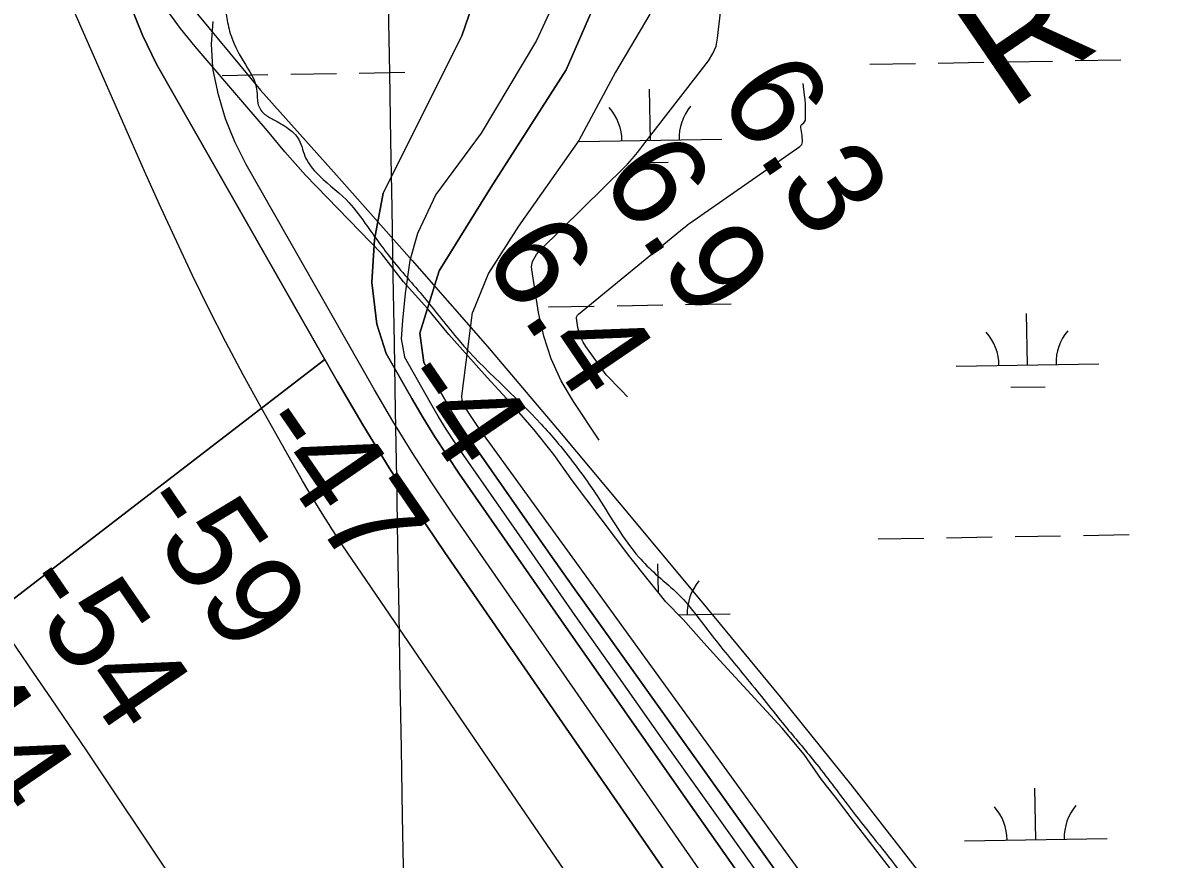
# Model space of a CAD drawing. Extents: x 3892998 to 3931244, y 278583 to 304547.
# Drawn here: x 3912822 to 3913620, y 291075 to 291661 of the extents above; entities that cross this region are included whole.
import ezdxf

# ---------------------------------------------------------------- set-up
doc = ezdxf.new("R2010")
doc.units = 0
for name, color, linetype in [('V-GRID-MAJR', 7, 'Continuous'), ('V-RIVR-EDGE', 7, 'Continuous'), ('V-RIVR-RANG', 7, 'Continuous'), ('V-RIVR-RANG-IDEN', 7, 'Continuous'), ('V-RRAP-FSHR', 7, 'Continuous'), ('V-TOPO-DPTH', 7, 'Continuous'), ('V-TOPO-MAJR', 7, 'Continuous'), ('V-TOPO-MINR', 7, 'Continuous'), ('V-TOPO-WATR', 7, 'Continuous'), ('V-WETL-SWMP', 7, 'Continuous')]:
    doc.layers.add(name, color=color, linetype=linetype)

msp = doc.modelspace()

# ---------------------------------------------------------------- linework, layer by layer
at = {"layer": 'V-GRID-MAJR'}
msp.add_spline([(3913205.694, 284291.167), (3913100.856, 290347.625), (3912995.9590000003, 296407.553), (3912891.061, 302467.47500000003), (3912891.001, 302470.95)], degree=3, dxfattribs=at)
at = {"layer": 'V-RIVR-EDGE'}
msp.add_spline([(3912905.462429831, 291820.09187449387), (3912916.1993131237, 291798.1348694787), (3912921.3932742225, 291786.9827471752), (3912931.4339568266, 291765.0274636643), (3912935.9162236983, 291747.61125666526), (3912940.4122626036, 291735.7646551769), (3912954.9722244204, 291711.36147947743), (3912961.5198530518, 291684.5413986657), (3912964.258175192, 291665.73709404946), (3912967.0128516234, 291653.54669597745), (3912976.0161192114, 291634.37879747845), (3912985.7104229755, 291613.1205754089), (3912986.385104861, 291604.416345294), (3912990.545093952, 291597.4440093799), (3912997.1486714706, 291593.25045095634), (3913007.576188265, 291586.9588221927), (3913014.1746012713, 291580.67666170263), (3913019.3633978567, 291567.43593733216), (3913026.994061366, 291556.2777897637), (3913048.1808410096, 291537.07976494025), (3913061.368198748, 291520.68634017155), (3913079.061924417, 291496.62351804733), (3913103.011127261, 291468.3679982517), (3913127.304126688, 291438.37111598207), (3913184.9441775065, 291379.7473732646), (3913206.1163243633, 291354.63164258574), (3913225.1955653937, 291327.780574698), (3913253.290124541, 291286.6350131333), (3913265.0962706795, 291274.77033585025), (3913279.3373977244, 291262.20343261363), (3913304.672976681, 291231.5077673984), (3913329.3132157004, 291201.16192403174), (3913355.687931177, 291168.3750744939), (3913376.51197769, 291143.26020456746), (3913400.8006733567, 291111.5228205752), (3913434.460534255, 291068.62298525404), (3913468.459887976, 291022.24128573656), (3913495.173235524, 290985.624471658), (3913514.60143765, 290959.12064336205), (3913570.4347088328, 290873.69747788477), (3913590.894300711, 290841.9695621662), (3913606.505449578, 290820.3486069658), (3913627.3217493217, 290792.10083393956), (3913641.190674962, 290769.7879818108), (3913669.62730919, 290726.20485708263), (3913686.621391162, 290700.7513550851), (3913705.714404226, 290679.46989270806), (3913722.034665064, 290663.06872116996), (3913741.1182098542, 290637.958155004), (3913763.668125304, 290606.9212754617), (3913781.0301049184, 290589.47322063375)], degree=3, dxfattribs=at)
at = {"layer": 'V-RRAP-FSHR'}
msp.add_lwpolyline([(3912906.2273111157, 291748.72141911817), (3912937.3302871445, 291675.2780910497), (3912988.1370711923, 291613.8770029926), (3913041.368687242, 291554.15732293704), (3913094.463087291, 291494.31885888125), (3913147.23595134, 291434.1936748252), (3913198.9479513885, 291373.15508276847), (3913250.2749274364, 291311.79495471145), (3913301.436015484, 291250.29351465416), (3913352.4148315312, 291188.64052259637), (3913402.6399835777, 291126.37722653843), (3913451.671151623, 291063.17799447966), (3913498.9103196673, 290998.61479441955), (3913544.746607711, 290933.480202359), (3913590.484591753, 290867.4137702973), (3913636.3208797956, 290801.84705023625)], dxfattribs=at)
at = {"layer": 'V-TOPO-DPTH'}
for points in [[(3913076.2252892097, 291429.3480772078), (3913069.6821606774, 291449.8861347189), (3913066.3242387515, 291479.06537268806), (3913068.1135175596, 291509.0898517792), (3913074.196726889, 291541.67761922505), (3913129.3501844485, 291651.7902147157), (3913156.5586192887, 291731.2995302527), (3913180.836297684, 291839.3435509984), (3913194.683691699, 291977.44226630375), (3913191.957129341, 292088.5559511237), (3913158.727274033, 292358.27516429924)], [(3913158.727274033, 292358.27516429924), (3913191.957129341, 292088.5559511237), (3913194.683691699, 291977.44226630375), (3913180.836297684, 291839.3435509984), (3913156.5586192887, 291731.2995302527), (3913129.3501844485, 291651.7902147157), (3913074.196726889, 291541.67761922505), (3913068.1135175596, 291509.0898517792), (3913066.3242387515, 291479.06537268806), (3913069.6821606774, 291449.8861347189), (3913076.2252892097, 291429.3480772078)], [(3912897.1451768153, 291673.0771983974), (3912905.4272677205, 291652.21579509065), (3912915.4203108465, 291631.9170253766), (3913041.9467947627, 291409.9072882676), (3913059.8933273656, 291379.3466368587), (3913078.3588966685, 291349.1123106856), (3913097.603021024, 291319.3674723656), (3913117.366182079, 291289.94895928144), (3913483.676371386, 290759.6812828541), (3913486.861552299, 290755.08465931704), (3913490.055569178, 290750.49420277), (3913493.2628400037, 290745.9129967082), (3913496.478946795, 290741.33795763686), (3913501.5266543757, 290734.17940441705), (3913502.217506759, 290733.1829194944), (3913502.897661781, 290732.1793083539), (3913504.2151823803, 290730.1435812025), (3913507.847480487, 290724.36477111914), (3913510.3003555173, 290720.4432378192), (3913512.741687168, 290716.51456646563), (3913515.165703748, 290712.5751880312), (3913517.578176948, 290708.6286715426), (3913604.584874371, 290565.5897350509), (3913651.4089650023, 290490.7297236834)], [(3912897.1451768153, 291673.0771983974), (3912905.4272677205, 291652.21579509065), (3912915.4203108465, 291631.9170253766), (3913033.3308464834, 291425.02526478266)], [(3913222.0146481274, 291673.01029888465), (3913202.394844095, 291628.0154578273), (3913149.6679661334, 291545.56635172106), (3913113.5076193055, 291487.0994041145), (3913099.8941203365, 291443.5911563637), (3913102.566354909, 291422.9241536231)], [(3913321.2006484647, 291030.7864036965), (3913122.5521167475, 291317.35974646), (3913108.2683274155, 291338.5591510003), (3913094.365688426, 291359.9986182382), (3913081.0347749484, 291381.7981795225), (3913068.085011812, 291403.8378035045), (3912978.057272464, 291561.80541846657), (3912970.2037428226, 291577.5384197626), (3912963.554142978, 291593.69153764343), (3912958.7104378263, 291610.4748304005), (3912955.0706624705, 291627.6782397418), (3912954.7258265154, 291629.9073004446), (3912953.863987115, 291646.025871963), (3912955.0475181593, 291661.7856191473)], [(3913321.2006484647, 291030.7864036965), (3913122.5521167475, 291317.35974646), (3913108.2683274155, 291338.5591510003), (3913094.365688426, 291359.9986182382), (3913081.0347749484, 291381.7981795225), (3913068.085011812, 291403.8378035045), (3912978.057272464, 291561.80541846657), (3912970.2037428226, 291577.5384197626), (3912963.554142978, 291593.69153764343), (3912958.7104378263, 291610.4748304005), (3912955.0706624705, 291627.6782397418), (3912954.7258265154, 291629.9073004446), (3912953.863987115, 291646.025871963), (3912955.0475181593, 291661.7856191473)], [(3913736.7739366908, 290460.95166721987), (3913565.6152656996, 290720.6767830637), (3913552.1224241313, 290740.91804081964), (3913538.4882412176, 290761.0625437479), (3913524.6420462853, 290781.0619144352), (3913510.6545100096, 290800.96453029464), (3913377.8013416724, 290987.8925058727), (3913332.7934826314, 291051.4249503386), (3913287.915268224, 291115.048546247), (3913243.2315207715, 291178.80886931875), (3913198.6774179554, 291242.6603438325), (3913127.6844999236, 291344.73357149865), (3913118.9028194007, 291357.7295626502), (3913110.359043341, 291370.87565585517), (3913102.1721239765, 291384.2469021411), (3913094.223109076, 291397.7682504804), (3913076.2252892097, 291429.3480772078)], [(3913076.2252892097, 291429.3480772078), (3913094.223109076, 291397.7682504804), (3913102.1721239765, 291384.2469021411), (3913110.359043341, 291370.87565585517), (3913118.9028194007, 291357.7295626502), (3913127.6844999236, 291344.73357149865), (3913198.6774179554, 291242.6603438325), (3913243.2315207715, 291178.80886931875), (3913287.915268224, 291115.048546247), (3913332.7934826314, 291051.4249503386), (3913377.8013416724, 290987.8925058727), (3913510.6545100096, 290800.96453029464), (3913524.6420462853, 290781.0619144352), (3913538.4882412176, 290761.0625437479), (3913552.1224241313, 290740.91804081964), (3913565.6152656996, 290720.6767830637), (3913736.7739366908, 290460.95166721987)], [(3913033.3308464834, 291425.02526478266), (3912690.2119734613, 291161.39650592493), (3912669.282087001, 291187.27087953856), (3912664.7268073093, 291192.0716686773), (3912659.769901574, 291196.3222000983), (3912654.2105567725, 291199.74734494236), (3912648.249585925, 291202.62223206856), (3912644.720916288, 291202.42653912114), (3912642.188392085, 291201.2770897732), (3912641.1500860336, 291198.6970058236), (3912641.1079254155, 291195.1631654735), (3912678.167616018, 291110.7816937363), (3912685.56900925, 291099.0881321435), (3912694.577744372, 291089.40111784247), (3912705.9974923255, 291082.72392447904), (3912719.024582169, 291078.0532784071), (3912727.0165259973, 291076.4848060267), (3912733.368369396, 291077.72723812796), (3912737.846777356, 291080.4629641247)], [(3912737.846777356, 291080.4629641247), (3912739.51503216, 291085.43863096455), (3912739.3098515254, 291091.9075916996), (3912734.4415513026, 291102.8483123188), (3912732.369312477, 291107.0518596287), (3912730.0886259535, 291111.12777709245), (3912727.495267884, 291115.0122497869), (3912724.693462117, 291118.76909263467), (3912693.004377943, 291157.94442237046), (3912690.2119734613, 291161.39650592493), (3913033.3308464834, 291425.02526478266), (3913036.6081723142, 291419.2747039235)], [(3913036.6081723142, 291419.2747039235), (3913041.9467947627, 291409.9072882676), (3913059.8933273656, 291379.3466368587), (3913078.3588966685, 291349.1123106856), (3913097.603021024, 291319.3674723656), (3913117.366182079, 291289.94895928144), (3913483.676371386, 290759.6812828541), (3913486.861552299, 290755.08465931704), (3913490.055569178, 290750.49420277), (3913493.2628400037, 290745.9129967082), (3913496.478946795, 290741.33795763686), (3913501.5266543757, 290734.17940441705), (3913502.217506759, 290733.1829194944), (3913502.897661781, 290732.1793083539), (3913504.2151823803, 290730.1435812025), (3913507.847480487, 290724.36477111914), (3913510.3003555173, 290720.4432378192), (3913512.741687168, 290716.51456646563), (3913515.165703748, 290712.5751880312), (3913517.578176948, 290708.6286715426), (3913604.584874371, 290565.5897350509), (3913651.4089650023, 290490.7297236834)], [(3913102.566354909, 291422.9241536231), (3913120.3614544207, 291391.69883888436), (3913123.305762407, 291386.6930337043), (3913126.3396415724, 291381.7438374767), (3913129.507877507, 291376.87955467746), (3913132.7656846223, 291372.07188083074), (3913158.6143120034, 291335.0286831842), (3913174.899976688, 291311.7675169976), (3913191.2339720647, 291288.5404514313), (3913207.6404634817, 291265.36453679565), (3913224.0952855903, 291242.2227227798), (3913515.117934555, 290834.28385512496), (3913535.8222699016, 290804.9764650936), (3913556.3448589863, 290775.54359221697), (3913576.5948286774, 290745.9224950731), (3913596.663052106, 290716.1759150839), (3913931.3713744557, 290215.07261771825)]]:
    msp.add_lwpolyline(points, dxfattribs=at)
at = {"layer": 'V-TOPO-MAJR'}
for points in [[(3913218.6467086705, 291041.66790410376), (3913171.143221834, 291111.083500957), (3913046.0044276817, 291294.6151204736), (3913038.594199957, 291305.7833975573), (3913031.375374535, 291317.07071063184), (3913024.4436525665, 291328.53657769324), (3913017.7033328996, 291340.1214807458), (3912988.677751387, 291391.4897516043), (3912976.100140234, 291414.3002910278), (3912963.843155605, 291437.27760166), (3912952.0671107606, 291460.5050691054), (3912940.611692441, 291483.89930775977), (3912929.509403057, 291507.4701883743), (3912918.55697275, 291531.1096387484), (3912907.8293310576, 291554.85194376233), (3912897.251548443, 291578.6628185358), (3912838.6385520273, 291712.3076241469)], [(3912484.064907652, 291701.969517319), (3912531.0426652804, 291634.52324090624), (3912577.9783023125, 291567.04764613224), (3912624.885858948, 291499.552505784), (3912816.6482854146, 291223.4422397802), (3912829.138379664, 291205.35373427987), (3912841.5627439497, 291187.2204542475), (3912853.8885132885, 291169.0200124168), (3912866.1485526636, 291150.7747960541), (3913226.975114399, 290610.63741017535), (3913234.3440935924, 290599.5889253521), (3913241.7022584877, 290588.5332544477), (3913249.0442019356, 290577.4668044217), (3913256.375331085, 290566.3931683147), (3913263.790301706, 290555.3787180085), (3913271.3277941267, 290544.4503112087), (3913279.0490692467, 290533.65096966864), (3913286.892866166, 290522.9376716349), (3913293.4498227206, 290514.13910575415), (3913304.5791366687, 290499.0302373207), (3913315.5952651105, 290483.8402416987), (3913326.4416152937, 290468.5285552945), (3913337.1747799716, 290453.1357417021), (3913674.6564096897, 289963.352789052)]]:
    msp.add_lwpolyline(points, dxfattribs=at)
at = {"layer": 'V-TOPO-MINR'}
for points in [[(3913076.2252892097, 291429.3480772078), (3913069.6821606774, 291449.8861347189), (3913066.3242387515, 291479.06537268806), (3913068.1135175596, 291509.0898517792), (3913074.196726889, 291541.67761922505), (3913129.3501844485, 291651.7902147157), (3913156.5586192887, 291731.2995302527), (3913180.836297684, 291839.3435509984), (3913194.683691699, 291977.44226630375), (3913191.957129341, 292088.5559511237), (3913158.727274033, 292358.27516429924)], [(3913204.929089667, 291699.22059100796), (3913181.651064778, 291648.65799932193), (3913142.9017367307, 291583.5481963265), (3913111.0676732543, 291540.72847929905), (3913098.1370872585, 291513.30545547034), (3913092.945335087, 291494.4429824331), (3913089.4580018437, 291471.2864515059), (3913087.696302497, 291452.4154969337), (3913086.806966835, 291439.5481659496), (3913088.9949535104, 291426.83734434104)], [(3913651.4089650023, 290490.7297236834), (3913604.584874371, 290565.5897350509), (3913517.578176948, 290708.6286715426), (3913515.165703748, 290712.5751880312), (3913512.741687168, 290716.51456646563), (3913510.3003555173, 290720.4432378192), (3913507.847480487, 290724.36477111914), (3913504.2151823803, 290730.1435812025), (3913502.897661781, 290732.1793083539), (3913502.217506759, 290733.1829194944), (3913501.5266543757, 290734.17940441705), (3913496.478946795, 290741.33795763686), (3913493.2628400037, 290745.9129967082), (3913490.055569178, 290750.49420277), (3913486.861552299, 290755.08465931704), (3913483.676371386, 290759.6812828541), (3913117.366182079, 291289.94895928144), (3913097.603021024, 291319.3674723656), (3913078.3588966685, 291349.1123106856), (3913059.8933273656, 291379.3466368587), (3913041.9467947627, 291409.9072882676), (3912915.4203108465, 291631.9170253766), (3912905.4272677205, 291652.21579509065), (3912897.1451768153, 291673.0771983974)], [(3913102.566354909, 291422.9241536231), (3913099.8941203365, 291443.5911563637), (3913113.5076193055, 291487.0994041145), (3913149.6679661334, 291545.56635172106), (3913202.394844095, 291628.0154578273), (3913222.0146481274, 291673.01029888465)], [(3913261.0166485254, 291666.9080774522), (3913236.906038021, 291626.42867638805), (3913211.2762163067, 291578.445806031), (3913169.109564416, 291518.4922651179), (3913148.0188132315, 291485.51262267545), (3913136.7595498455, 291458.03431484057)], [(3913321.2006484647, 291030.7864036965), (3913122.5521167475, 291317.35974646), (3913108.2683274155, 291338.5591510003), (3913094.365688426, 291359.9986182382), (3913081.0347749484, 291381.7981795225), (3913068.085011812, 291403.8378035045), (3912978.057272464, 291561.80541846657), (3912970.2037428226, 291577.5384197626), (3912963.554142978, 291593.69153764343), (3912958.7104378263, 291610.4748304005), (3912955.0706624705, 291627.6782397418), (3912954.7258265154, 291629.9073004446), (3912953.863987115, 291646.025871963), (3912955.0475181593, 291661.7856191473)], [(3913245.4350105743, 291398.95718784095), (3913240.9572710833, 291403.62288618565), (3913230.512254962, 291414.41400825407), (3913216.1935101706, 291434.0846827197), (3913214.255856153, 291437.19376951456), (3913212.636547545, 291440.43446424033), (3913211.494757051, 291443.8725708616), (3913210.6713119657, 291447.4422854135), (3913209.656692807, 291453.9438799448), (3913209.6630639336, 291454.7648358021), (3913210.402126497, 291456.2398277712), (3913210.9990853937, 291456.83479993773), (3913285.0161179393, 291517.49340941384), (3913285.513709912, 291517.89953629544), (3913287.5199829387, 291519.50397043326), (3913288.549579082, 291520.27099635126), (3913289.0732155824, 291520.6426452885), (3913366.1494984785, 291574.21028586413), (3913367.5101032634, 291575.71094338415), (3913368.0749473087, 291577.6562375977), (3913367.8244479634, 291582.0131090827), (3913366.8746186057, 291587.52955436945), (3913366.908304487, 291588.3870003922), (3913367.1278338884, 291589.14745613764), (3913367.6261285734, 291589.762426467), (3913369.0385578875, 291590.7947642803), (3913369.9377091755, 291592.18420983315), (3913370.1085693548, 291593.05929762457), (3913370.1809360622, 291597.5302046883), (3913370.1677666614, 291600.73774668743), (3913370.06807204, 291603.9408380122), (3913369.8385895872, 291607.1372533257), (3913369.522581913, 291610.32921796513), (3913368.5440589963, 291618.5153384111)], [(3913620.1941250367, 290714.21305653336), (3913594.736994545, 290750.0982914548), (3913569.19605935, 290785.9235571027), (3913543.5294171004, 290821.6588688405), (3913517.7789701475, 290857.33421130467), (3913148.9031195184, 291366.4973075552), (3913146.437676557, 291369.91851225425), (3913143.9837869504, 291373.34793985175), (3913141.547227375, 291376.78970179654), (3913139.122221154, 291380.23968664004), (3913135.287172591, 291385.7250522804), (3913134.3235224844, 291387.1734852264), (3913133.8688546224, 291387.9148784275), (3913133.4277653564, 291388.66485999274), (3913130.4900239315, 291393.82214557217), (3913129.43825995, 291396.49498069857), (3913129.2879027, 291399.34639505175), (3913136.7595498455, 291458.03431484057)], [(3913736.7739366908, 290460.95166721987), (3913565.6152656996, 290720.6767830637), (3913552.1224241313, 290740.91804081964), (3913538.4882412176, 290761.0625437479), (3913524.6420462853, 290781.0619144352), (3913510.6545100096, 290800.96453029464), (3913377.8013416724, 290987.8925058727), (3913332.7934826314, 291051.4249503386), (3913287.915268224, 291115.048546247), (3913243.2315207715, 291178.80886931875), (3913198.6774179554, 291242.6603438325), (3913127.6844999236, 291344.73357149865), (3913118.9028194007, 291357.7295626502), (3913110.359043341, 291370.87565585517), (3913102.1721239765, 291384.2469021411), (3913094.223109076, 291397.7682504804), (3913076.2252892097, 291429.3480772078)], [(3913831.8149811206, 290340.75298341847), (3913581.120458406, 290718.41441440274), (3913564.348268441, 290743.4135949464), (3913547.4135816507, 290768.3010322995), (3913530.235149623, 290793.020854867), (3913512.8942207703, 290817.6289342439), (3913300.39997266, 291116.0492439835), (3913269.7595659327, 291159.22065063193), (3913239.2082944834, 291202.4548381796), (3913208.790725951, 291245.7831970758), (3913178.462292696, 291289.17433687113), (3913130.2312612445, 291358.4063613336), (3913124.2086764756, 291367.3065502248), (3913118.3504509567, 291376.31052812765), (3913112.738764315, 291385.47018954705), (3913107.2914369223, 291394.73363997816), (3913088.9949535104, 291426.83734434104)], [(3913931.3713744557, 290215.07261771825), (3913596.663052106, 290716.1759150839), (3913576.5948286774, 290745.9224950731), (3913556.3448589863, 290775.54359221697), (3913535.8222699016, 290804.9764650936), (3913515.117934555, 290834.28385512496), (3913224.0952855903, 291242.2227227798), (3913207.6404634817, 291265.36453679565), (3913191.2339720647, 291288.5404514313), (3913174.899976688, 291311.7675169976), (3913158.6143120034, 291335.0286831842), (3913132.7656846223, 291372.07188083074), (3913129.507877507, 291376.87955467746), (3913126.3396415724, 291381.7438374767), (3913123.305762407, 291386.6930337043), (3913120.3614544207, 291391.69883888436), (3913102.566354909, 291422.9241536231)]]:
    msp.add_lwpolyline(points, dxfattribs=at)
at = {"layer": 'V-TOPO-WATR'}
msp.add_lwpolyline([(3913225.6005556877, 291368.6369424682), (3913207.49845632, 291395.5251343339), (3913198.9722506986, 291410.2008588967), (3913191.8184513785, 291425.4147784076), (3913186.723261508, 291441.43599034), (3913183.0004779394, 291457.9953972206), (3913178.305176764, 291488.0619798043), (3913178.2009628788, 291489.9731909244), (3913178.8443998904, 291493.6463914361), (3913180.608402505, 291497.0832923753), (3913181.7151430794, 291498.6899514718), (3913184.2901796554, 291501.6302598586), (3913243.7297483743, 291560.31631210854), (3913245.417457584, 291562.03495460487), (3913248.6646951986, 291565.58934369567), (3913250.224223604, 291567.42509029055), (3913253.2581169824, 291571.1708717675), (3913256.2318036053, 291574.96462660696), (3913302.0878328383, 291634.4386828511), (3913305.12194847, 291639.3813491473), (3913307.404756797, 291644.56482865), (3913308.5606041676, 291650.10952796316), (3913317.954252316, 291732.66030001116)], dxfattribs=at)
at = {"layer": 'V-WETL-SWMP'}
for p, q in [((3912932.1329983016, 291656.95099870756), (3912922.8489983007, 291669.79999870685)), ((3912942.5149982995, 291644.4089987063), (3912932.1329983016, 291656.95099870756)), ((3912977.182998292, 291603.8029987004), (3912942.5149982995, 291644.4089987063)), ((3913463.1888564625, 291632.7979327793), (3913495.184063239, 291633.351774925)), ((3913511.1816666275, 291633.6286959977), (3913543.176873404, 291634.1825381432)), ((3913559.1744767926, 291634.45945921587), (3913591.169683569, 291635.01330136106)), ((3913009.3488465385, 291624.94188963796), (3913041.3440533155, 291625.4957317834)), ((3913057.3416567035, 291625.77265285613), (3913089.33686348, 291626.3264950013)), ((3913415.1960462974, 291631.96716956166), (3913447.1912530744, 291632.52101170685)), ((3912961.356036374, 291624.11112641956), (3912993.3512431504, 291624.6649685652)), ((3913261.505423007, 291578.55715868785), (3913260.8823505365, 291614.55176632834)), ((3912993.104998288, 291585.1919986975), (3912977.182998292, 291603.8029987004)), ((3913005.3019982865, 291570.4609986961), (3912993.104998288, 291585.1919986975)), ((3913211.512912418, 291577.69178033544), (3913311.497933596, 291579.42253704)), ((3913019.8089982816, 291554.2419986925), (3913005.3019982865, 291570.4609986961)), ((3913249.7742935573, 291562.92077925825), (3913273.7706986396, 291563.3361608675)), ((3913073.072998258, 291499.44399867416), (3913019.8089982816, 291554.24199869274)), ((3913088.503998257, 291479.4299986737), (3913073.072998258, 291499.44399867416)), ((3913105.0249982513, 291461.1229986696), (3913088.503998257, 291479.4299986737)), ((3913120.2479982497, 291442.50799866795), (3913105.0249982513, 291461.1229986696)), ((3913190.1062659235, 291461.871935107), (3913222.1014727, 291462.4257772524)), ((3913238.0990760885, 291462.7026983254), (3913270.094282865, 291463.25654047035)), ((3913286.0918862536, 291463.5334615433), (3913318.08709303, 291464.0873036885)), ((3913525.7037006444, 291421.2442247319), (3913525.080628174, 291457.23883237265)), ((3913147.1459982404, 291412.5589986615), (3913120.2479982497, 291442.50799866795)), ((3913475.7111900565, 291420.37884637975), (3913575.6962112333, 291422.10960308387)), ((3913166.182998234, 291391.76699865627), (3913147.1459982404, 291412.5589986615)), ((3913513.9725711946, 291405.6078453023), (3913537.9689762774, 291406.0232269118)), ((3913179.9879982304, 291375.84399865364), (3913166.182998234, 291391.76699865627)), ((3913193.801998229, 291358.5209986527), (3913179.9879982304, 291375.84399865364)), ((3913206.921998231, 291340.0929986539), (3913193.801998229, 291358.5209986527)), ((3913246.969998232, 291286.81399865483), (3913206.921998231, 291340.0929986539)), ((3913420.953841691, 291299.3420002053), (3913452.949048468, 291299.8958423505)), ((3913468.946651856, 291300.17276342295), (3913500.9418586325, 291300.72660556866)), ((3913516.939462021, 291301.00352664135), (3913548.9346687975, 291301.55736878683)), ((3913564.932272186, 291301.8342898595), (3913596.9274789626, 291302.38813200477)), ((3913259.875998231, 291270.68599865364), (3913246.969998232, 291286.81399865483)), ((3913266.98816047, 291261.8219583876), (3913266.64014593, 291281.926596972)), ((3913272.1769982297, 291255.35499865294), (3913259.875998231, 291270.68599865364)), ((3913284.4589982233, 291242.9239986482), (3913272.176998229, 291255.3549986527)), ((3913281.247886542, 291246.1740661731), (3913317.2557289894, 291246.79736768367)), ((3913298.966998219, 291226.6059986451), (3913284.4589982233, 291242.9239986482)), ((3913310.0489982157, 291214.26799864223), (3913298.966998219, 291226.6059986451)), ((3913353.6629982, 291166.81399863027), (3913310.0489982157, 291214.26799864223)), ((3913369.184998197, 291148.20099862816), (3913353.6629982, 291166.81399863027)), ((3913381.2979981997, 291130.8679986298), (3913369.184998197, 291148.20099862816)), ((3913391.0789981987, 291118.5219986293), (3913381.2979981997, 291130.8679986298)), ((3913531.461496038, 291088.6190553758), (3913530.8384235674, 291124.6136630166)), ((3913403.4859981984, 291102.0899986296), (3913391.0789981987, 291118.5219986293)), ((3913435.2559981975, 291060.8669986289), (3913403.4859981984, 291102.0899986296)), ((3913481.46898545, 291087.75367702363), (3913581.4540066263, 291089.48443372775))]:
    msp.add_line(p, q, dxfattribs=at)
for centre, radius, start, end in [((3913206.2625439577, 291578.07576993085), 35.24628790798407, 0.2198800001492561, 41.763538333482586), ((3913316.731866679, 291579.9880115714), 35.246287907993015, 140.21987699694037, 181.7635353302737), ((3913470.4608215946, 291420.7628359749), 35.24628790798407, 0.2198800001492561, 41.763538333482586), ((3913580.930144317, 291422.6750776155), 35.246287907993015, 140.21987699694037, 181.7635353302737), ((3913322.4896620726, 291247.36284221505), 35.246287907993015, 140.21987699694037, 181.7635353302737), ((3913476.218616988, 291088.13766661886), 35.24628790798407, 0.2198800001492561, 41.763538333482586), ((3913586.6879397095, 291090.0499082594), 35.246287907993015, 140.21987699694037, 181.7635353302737)]:
    msp.add_arc(centre, radius, start, end, dxfattribs=at)

# ---------------------------------------------------------------- texts
at = {"layer": 'V-RIVR-RANG'}
for s, height, rotation, p in [('6.3', 67.00000000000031, 304.1883257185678, (3913307.7351558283, 291609.19172234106)), ('6.9', 67.00000000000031, 304.1883257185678, (3913225.0079341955, 291553.0119194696)), ('6.4', 67.00000000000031, 304.1883257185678, (3913142.577155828, 291496.3967223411)), ('-4', 67, 304.4729722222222, (3913080.345317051, 291409.61261783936)), ('-47', 67, 304.4729722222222, (3912981.037605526, 291377.57965872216)), ('-59', 67, 304.4729722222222, (3912897.5694679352, 291322.4766702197)), ('-54', 67, 304.4729722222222, (3912814.990467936, 291266.0796702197)), ('-44', 67, 304.4729722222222, (3912733.605898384, 291207.94200565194))]:
    msp.add_text(s, height=height, rotation=rotation, dxfattribs=at).set_placement(p)
at = {"layer": 'V-RIVR-RANG-IDEN'}
msp.add_text('R-11.2', height=82.99999799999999, rotation=34.33123832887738, dxfattribs=at).set_placement((3913512.2708946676, 291598.99928388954))

doc.saveas('drawing.dxf')
